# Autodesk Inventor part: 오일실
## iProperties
IsCustomPart: 1
Company: 한국ATC센터
Created: 2014-11
Part Number: 오일실
Material: 고무
Description: 오일-실
Document SubType Name: Modeling
Standard: KS B 2804
Designer: KYOUNG IL JANG
Standards Organization: KS
Language: ko-KR
Size Designation: S - 25 40 8
Categories: <MemberInstance><Categories><Category DisplayName="샤프트 부품" InternalName="7f7aeb1f-a693-4053-b835-cee3144e0d98" Mnemonic="SHFT"><Category DisplayName="실링" Intern
Density: 0.93 g/cm^3
Mass: 2.48215 g
Surface Area: 40.3381 cm^2
Volume: 2.66898 cm^3
Author: KYOUNG IL JANG
